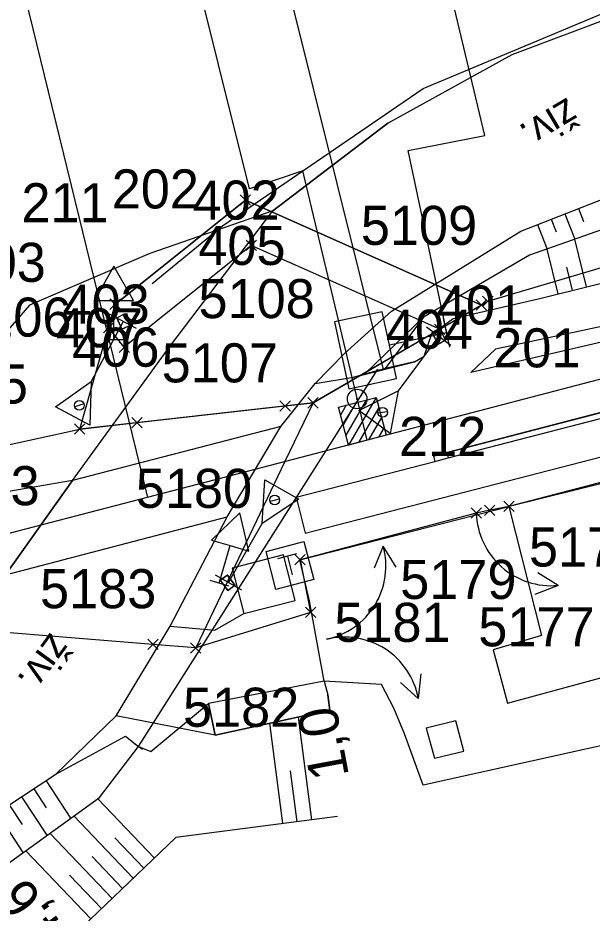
# Model space of a CAD drawing. Extents: x -806456 to -805395, y -1150847 to -1150506.
# Drawn here: x -806176.16 to -806146.78, y -1150729.15 to -1150683.33 of the extents above; entities that cross this region are included whole.
import ezdxf

# ---------------------------------------------------------------- set-up
doc = ezdxf.new("R2010")
doc.units = 0
for name, color, linetype in [('0381KM032-037P - Vrstva 1', 7, 'Continuous'), ('0381KM032-037P - Vrstva 12', 7, 'Continuous'), ('0381KM032-037P - Vrstva 14', 7, 'Continuous'), ('0381KM032-037P - Vrstva 16', 7, 'Continuous'), ('0381KM032-037P - Vrstva 17', 7, 'Continuous'), ('0381KM032-037P - Vrstva 19', 7, 'Continuous'), ('0381KM032-037P - Vrstva 23', 7, 'Continuous'), ('0381KM032-037P - Vrstva 27', 7, 'Continuous'), ('0381KM032-037P - Vrstva 3', 7, 'Continuous'), ('0381KM032-037P - Vrstva 33', 7, 'Continuous'), ('0381KM032-037P - Vrstva 4', 7, 'Continuous'), ('0381KM032-037P - Vrstva 48', 7, 'Continuous'), ('0381KM032-037P - Vrstva 49', 7, 'Continuous'), ('0381KM032-037P - Vrstva 51', 7, 'Continuous'), ('0381KM032-037P - Vrstva 55', 7, 'Continuous'), ('0381KM032-037P - Vrstva 7', 7, 'Continuous'), ('DZ - DZ_krizek', 7, 'Continuous'), ('DZ - DZ_ostat', 7, 'Continuous'), ('DZ - DZ_číslo', 7, 'Continuous'), ('szdc - hran DP', 7, 'Continuous'), ('szdc - szdc_cislo', 7, 'Continuous'), ('szdc - szdc_krizek', 7, 'Continuous'), ('VB - VB', 7, 'Continuous'), ('VB - VB_cislo', 7, 'Continuous'), ('VB - VB_krizek', 7, 'Continuous')]:
    doc.layers.add(name, color=color, linetype=linetype)

msp = doc.modelspace()

# ---------------------------------------------------------------- linework, layer by layer
at = {"layer": '0381KM032-037P - Vrstva 1'}
msp.add_lwpolyline([(-805989.76, -1150661.17), (-806027.03, -1150670.9), (-806064.32, -1150680.56), (-806101.67, -1150690.24), (-806138.44, -1150699.75), (-806158.28, -1150704.94), (-806163.64, -1150706.34), (-806175.38, -1150709.4), (-806186.46, -1150712.29), (-806205.201, -1150717.188), (-806213.26, -1150719.29)], dxfattribs=at)
at = {"layer": '0381KM032-037P - Vrstva 12'}
for p, q in [((-806171.097, -1150698.685), (-806170.698, -1150698.477)), ((-806170.424, -1150699.073), (-806170.42, -1150699.072)), ((-806154.576, -1150699.231), (-806154.576, -1150699.231)), ((-806154.655, -1150700.027), (-806154.654, -1150700.027)), ((-806165.431, -1150711.842), (-806165.798, -1150712.11)), ((-806165.431, -1150711.842), (-806165.452, -1150711.852)), ((-806165.431, -1150711.842), (-806165.054, -1150712.367)), ((-806165.411, -1150712.643), (-806165.409, -1150712.642))]:
    msp.add_line(p, q, dxfattribs=at)
for points in [[(-806171.096, -1150698.684), (-806170.697, -1150698.478), (-806170.42, -1150699.072), (-806170.837, -1150699.265), (-806171.096, -1150698.684), (-806171.097, -1150698.685), (-806170.836, -1150699.265), (-806170.837, -1150699.265)], [(-806170.836, -1150699.265), (-806170.424, -1150699.073), (-806170.698, -1150698.477), (-806170.697, -1150698.478)], [(-806154.955, -1150699.45), (-806154.576, -1150699.231), (-806154.27, -1150699.815), (-806154.654, -1150700.027), (-806154.955, -1150699.45), (-806154.958, -1150699.45), (-806154.655, -1150700.027), (-806154.267, -1150699.814), (-806154.27, -1150699.815)], [(-806154.267, -1150699.814), (-806154.576, -1150699.231), (-806154.958, -1150699.45)], [(-806165.796, -1150712.109), (-806165.452, -1150711.852), (-806165.062, -1150712.372), (-806165.411, -1150712.643), (-806165.796, -1150712.109), (-806165.798, -1150712.11), (-806165.409, -1150712.642), (-806165.054, -1150712.367), (-806165.062, -1150712.372)]]:
    msp.add_lwpolyline(points, dxfattribs=at)
at = {"layer": '0381KM032-037P - Vrstva 14'}
for p, q in [((-806161.449, -1150709.693), (-806093.878, -1150692.3)), ((-806154.198, -1150705.574), (-806154.133, -1150705.838)), ((-806161.922, -1150707.857), (-806154.816, -1150706.033)), ((-806161.922, -1150707.857), (-806161.449, -1150709.693))]:
    msp.add_line(p, q, dxfattribs=at)
for points in [[(-806154.886, -1150705.756), (-806154.199, -1150705.575), (-806132.573, -1150699.952), (-806108.128, -1150693.694), (-806094.432, -1150690.13), (-806092.838, -1150689.765), (-806094.431, -1150690.13), (-806108.117, -1150693.693), (-806132.574, -1150699.948), (-806154.198, -1150705.574), (-806154.884, -1150705.755)], [(-806154.816, -1150706.033), (-806154.133, -1150705.838), (-806132.472, -1150700.244), (-806108.057, -1150693.975), (-806094.307, -1150690.424), (-806092.667, -1150690.003)], [(-806154.816, -1150706.033), (-806154.137, -1150705.844), (-806132.472, -1150700.244)], [(-806154.886, -1150705.756), (-806154.884, -1150705.755), (-806154.816, -1150706.033)]]:
    msp.add_lwpolyline(points, dxfattribs=at)
at = {"layer": '0381KM032-037P - Vrstva 16'}
for p, q in [((-806160.478, -1150717.283), (-806166.409, -1150718.419)), ((-806160.198, -1150718.758), (-806160.293, -1150717.983)), ((-806166.409, -1150718.419), (-806166.069, -1150720.047)), ((-806166.069, -1150720.047), (-806160.198, -1150718.758))]:
    msp.add_line(p, q, dxfattribs=at)
msp.add_lwpolyline([(-806166.069, -1150720.047), (-806171.128, -1150719.056), (-806168.37, -1150714.464), (-806166.085, -1150714.657), (-806164.602, -1150713.817)], dxfattribs=at)
msp.add_lwpolyline([(-806153.75, -1150719.31), (-806155.265, -1150719.685), (-806154.836, -1150721.222), (-806153.334, -1150720.858)], close=True, dxfattribs=at)
at = {"layer": '0381KM032-037P - Vrstva 17'}
for q in [(-806149.551, -1150711.723), (-806149.698, -1150712.832)]:
    msp.add_line((-806148.519, -1150712.375), q, dxfattribs=at)
for points in [[(-806169.284, -1150696.914), (-806165.684, -1150693.969), (-806155.413, -1150686.939), (-806141.029, -1150680.901), (-806121.846, -1150675.136), (-806106.33, -1150670.053), (-806095.392, -1150665.453)], [(-806160.478, -1150717.283), (-806161.235, -1150713.172), (-806161.722, -1150711.057), (-806151.035, -1150708.341)], [(-806156.804, -1150711.439), (-806157.463, -1150710.359), (-806157.921, -1150711.49)], [(-806155.547, -1150716.896), (-806155.668, -1150718.155), (-806156.574, -1150717.337)]]:
    msp.add_lwpolyline(points, dxfattribs=at)
for centre, start, end in [((-806148.868, -1150708.556), 181.714, 275.2338), ((-806161.159, -1150711.38), 281.9322, 15.4521), ((-806159.438, -1150718.852), 10.4818, 104.0016)]:
    msp.add_arc(centre, 3.834, start, end, dxfattribs=at)
at = {"layer": '0381KM032-037P - Vrstva 19'}
for p, q in [((-806157.446, -1150701.329), (-806169.593, -1150652.631)), ((-806169.987, -1150720.615), (-806157.733, -1150701.3)), ((-806158.404, -1150701.543), (-806157.373, -1150701.28)), ((-806158.4, -1150701.548), (-806158.404, -1150701.543)), ((-806157.368, -1150701.279), (-806157.373, -1150701.28)), ((-806170.188, -1150720.467), (-806169.786, -1150720.763))]:
    msp.add_line(p, q, dxfattribs=at)
for points in [[(-806158.982, -1150701.712), (-806155.863, -1150700.934), (-806157.368, -1150701.279)], [(-806158.982, -1150701.712), (-806158.4, -1150701.548)]]:
    msp.add_lwpolyline(points, dxfattribs=at)
at = {"layer": '0381KM032-037P - Vrstva 23'}
for points in [[(-806142.07, -1150715.951), (-806143.104, -1150712.223), (-806134.891, -1150710.09), (-806136.286, -1150704.548), (-806144.528, -1150706.669), (-806144.577, -1150706.639), (-806151.035, -1150708.341), (-806149.366, -1150714.939), (-806151.841, -1150715.669), (-806151.103, -1150718.404)], [(-806162.56, -1150710.816), (-806165.198, -1150711.492), (-806164.602, -1150713.817), (-806161.964, -1150713.141)]]:
    msp.add_lwpolyline(points, close=True, dxfattribs=at)
at = {"layer": '0381KM032-037P - Vrstva 27'}
msp.add_line((-806158.849, -1150702.829), (-806158.749, -1150702.829), dxfattribs=at)
msp.add_circle((-806158.799, -1150702.829), 0.5, dxfattribs=at)
at = {"layer": '0381KM032-037P - Vrstva 3'}
for p, q in [((-806158.331, -1150702.886), (-806159.381, -1150704.68)), ((-806157.818, -1150702.752), (-806159.248, -1150705.193)), ((-806159.357, -1150703.154), (-806159.65, -1150703.653)), ((-806158.844, -1150703.02), (-806159.516, -1150704.166)), ((-806157.684, -1150703.265), (-806158.735, -1150705.059)), ((-806157.55, -1150703.779), (-806158.221, -1150704.925)), ((-806157.416, -1150704.292), (-806157.708, -1150704.791))]:
    msp.add_line(p, q, dxfattribs=at)
msp.add_lwpolyline([(-806158.28, -1150704.94), (-806161.571, -1150691.159), (-806164.309, -1150692.072), (-806173.835, -1150653.806)], dxfattribs=at)
msp.add_lwpolyline([(-806157.312, -1150704.687), (-806159.248, -1150705.193), (-806159.753, -1150703.258), (-806157.818, -1150702.752)], close=True, dxfattribs=at)
at = {"layer": '0381KM032-037P - Vrstva 33'}
for p, q in [((-806162.85, -1150710.997), (-806161.882, -1150710.745)), ((-806162.366, -1150710.871), (-806162.114, -1150711.839))]:
    msp.add_line(p, q, dxfattribs=at)
msp.add_lwpolyline([(-806163.46, -1150710.64), (-806161.525, -1150710.135), (-806161.02, -1150712.07), (-806162.955, -1150712.575), (-806163.46, -1150710.64)], dxfattribs=at)
at = {"layer": '0381KM032-037P - Vrstva 4'}
for p, q in [((-806169.501, -1150707.868), (-806182.162, -1150656.159)), ((-806170.089, -1150699.232), (-806171.461, -1150698.498)), ((-806154, -1150700.092), (-806155.244, -1150699.156)), ((-806172.782, -1150703.087), (-806173.251, -1150703.226)), ((-806157.253, -1150703.488), (-806157.738, -1150703.554)), ((-806163.25, -1150708.061), (-806162.777, -1150707.935)), ((-806166.06, -1150711.832), (-806164.71, -1150712.606))]:
    msp.add_line(p, q, dxfattribs=at)
for points in [[(-806107.829, -1150689.094), (-806118.691, -1150691.974), (-806137.278, -1150697.201), (-806151.726, -1150700.277), (-806152.972, -1150701.484)], [(-806107.781, -1150690.049), (-806118.339, -1150693.119), (-806137.186, -1150697.806), (-806152.972, -1150701.484)], [(-806170.775, -1150698.865), (-806172.404, -1150701.937), (-806172.472, -1150704.171), (-806174.24, -1150703.24), (-806172.404, -1150701.937)], [(-806154.622, -1150699.624), (-806156.703, -1150702.409), (-806157.114, -1150704.607), (-806158.718, -1150703.416), (-806156.703, -1150702.409)], [(-806173.358, -1150707), (-806179.992, -1150708.144), (-806186.437, -1150710.716), (-806215.256, -1150718.168), (-806230.349, -1150722.089), (-806238.693, -1150724.411)], [(-806165.385, -1150712.219), (-806163.663, -1150709.198), (-806163.526, -1150706.967), (-806161.788, -1150707.952), (-806163.663, -1150709.198)]]:
    msp.add_lwpolyline(points, dxfattribs=at)
msp.add_lwpolyline([(-806165.452, -1150708.868), (-806162.708, -1150704.236), (-806173.358, -1150707), (-806176.794, -1150711.837)], close=True, dxfattribs=at)
for centre in [(-806173.016, -1150703.155), (-806157.495, -1150703.519), (-806163.014, -1150707.999)]:
    msp.add_circle(centre, 0.248, dxfattribs=at)
at = {"layer": '0381KM032-037P - Vrstva 48'}
for p, q in [((-806147.468, -1150693.088), (-806147.21, -1150693.749)), ((-806148.865, -1150693.634), (-806148.616, -1150694.271)), ((-806148.167, -1150693.361), (-806147.66, -1150694.659)), ((-806149.564, -1150693.907), (-806149.076, -1150695.157)), ((-806147.054, -1150697.098), (-806147.659, -1150694.659)), ((-806148.51, -1150697.459), (-806149.081, -1150695.159)), ((-806147.782, -1150697.279), (-806148.076, -1150696.094)), ((-806162.608, -1150724.567), (-806163.272, -1150719.433)), ((-806161.12, -1150724.375), (-806161.801, -1150719.11)), ((-806161.864, -1150724.471), (-806162.2, -1150721.871)), ((-806174.716, -1150722.377), (-806173.459, -1150724.29)), ((-806175.343, -1150722.788), (-806174.706, -1150723.758)), ((-806175.97, -1150723.2), (-806174.679, -1150725.165)), ((-806169.169, -1150726.326), (-806172.068, -1150723.292)), ((-806176.597, -1150723.612), (-806175.943, -1150724.607)), ((-806177.223, -1150724.024), (-806175.899, -1150726.04)), ((-806170.253, -1150727.362), (-806173.299, -1150724.175)), ((-806171.338, -1150728.398), (-806174.53, -1150725.058)), ((-806169.711, -1150726.844), (-806171.197, -1150725.288)), ((-806172.423, -1150729.435), (-806175.761, -1150725.941)), ((-806170.796, -1150727.88), (-806172.355, -1150726.248)), ((-806171.88, -1150728.916), (-806173.513, -1150727.208))]:
    msp.add_line(p, q, dxfattribs=at)
at = {"layer": '0381KM032-037P - Vrstva 49'}
for q in [(-806158.4, -1150701.548), (-806157.368, -1150701.279)]:
    msp.add_line((-806155.41, -1150698.652), q, dxfattribs=at)
for points in [[(-806106.833, -1150681.791), (-806120.865, -1150686.009), (-806130.84, -1150689.204), (-806140.721, -1150692.217), (-806149.976, -1150695.474), (-806155.41, -1150698.652)], [(-806160.94, -1150702.044), (-806159.44, -1150700.497), (-806157.039, -1150698.345), (-806150.424, -1150694.243), (-806141.479, -1150690.749), (-806131.125, -1150687.358), (-806121.483, -1150684.155)], [(-806155.863, -1150700.934), (-806155.366, -1150700.637), (-806154.958, -1150699.45), (-806154.576, -1150699.231), (-806153.885, -1150698.711), (-806149.376, -1150697.674), (-806139.489, -1150695.222), (-806130.934, -1150692.921), (-806118.589, -1150689.919), (-806108.264, -1150688.165)], [(-806157.224, -1150688.717), (-806163.106, -1150693.208), (-806169.402, -1150695.384), (-806175.562, -1150698.028), (-806181.812, -1150705.214), (-806196.093, -1150709.847), (-806203.772, -1150712.233), (-806204.393, -1150713.538)], [(-806086.941, -1150691.888), (-806103.092, -1150696.78), (-806110.097, -1150699.269), (-806113.941, -1150700.3), (-806116.978, -1150701.29), (-806117.569, -1150702.15), (-806117.466, -1150702.7), (-806118.52, -1150712.146), (-806144.328, -1150720.147), (-806155.423, -1150722.604), (-806156.372, -1150719.964), (-806156.921, -1150718.664), (-806157.558, -1150717.448), (-806160.478, -1150717.283), (-806160.293, -1150717.983), (-806160.198, -1150718.758), (-806166.069, -1150720.047), (-806166.409, -1150718.419)], [(-806160.94, -1150702.044), (-806158.982, -1150701.712)], [(-806169.987, -1150720.615), (-806169.362, -1150720.879), (-806166.409, -1150718.419)], [(-806174.208, -1150722.043), (-806170.645, -1150720.091), (-806169.987, -1150720.615)], [(-806193.249, -1150733.077), (-806185.745, -1150730.772), (-806177.154, -1150726.94), (-806171.988, -1150723.234), (-806169.987, -1150720.615)], [(-806194.182, -1150731.583), (-806186.226, -1150728.982), (-806178.594, -1150724.924), (-806174.208, -1150722.043)], [(-806159.8, -1150724.204), (-806168.067, -1150725.273), (-806174.063, -1150731.002)]]:
    msp.add_lwpolyline(points, dxfattribs=at)
at = {"layer": '0381KM032-037P - Vrstva 51'}
for p, q in [((-806171.742, -1150699.79), (-806170.742, -1150699.79)), ((-806166.34, -1150712.113), (-806165.38, -1150712.395))]:
    msp.add_line(p, q, dxfattribs=at)
for points in [[(-806195.218, -1150723.443), (-806183.651, -1150718.077), (-806179.484, -1150714.678), (-806176.794, -1150711.837), (-806173.358, -1150707), (-806168.375, -1150700.145), (-806163.106, -1150693.208), (-806157.224, -1150688.717), (-806150.874, -1150685.207), (-806140.159, -1150681.153)], [(-806194.182, -1150731.583), (-806186.226, -1150728.982), (-806178.594, -1150724.924), (-806174.208, -1150722.043), (-806171.128, -1150719.056), (-806168.37, -1150714.464), (-806165.452, -1150708.868), (-806162.708, -1150704.236), (-806160.94, -1150702.044), (-806159.44, -1150700.497), (-806157.039, -1150698.345), (-806150.424, -1150694.243), (-806141.479, -1150690.749), (-806131.125, -1150687.358), (-806121.483, -1150684.155)], [(-806171.242, -1150699.79), (-806171.242, -1150697.79), (-806170.242, -1150697.79), (-806171.242, -1150696.04), (-806172.242, -1150697.79), (-806171.242, -1150697.79)], [(-806165.86, -1150712.254), (-806165.296, -1150710.335), (-806164.337, -1150710.617), (-806164.803, -1150708.656), (-806166.256, -1150710.053), (-806165.296, -1150710.335)]]:
    msp.add_lwpolyline(points, dxfattribs=at)
at = {"layer": '0381KM032-037P - Vrstva 55'}
msp.add_lwpolyline([(-806161.05, -1150703.03), (-806162.49, -1150706.04), (-806167.06, -1150715.57)], dxfattribs=at)
at = {"layer": '0381KM032-037P - Vrstva 7'}
msp.add_line((-806154.057, -1150700.177), (-806154.373, -1150698.711), dxfattribs=at)
for points in [[(-806154.215, -1150699.444), (-806156.181, -1150690.115), (-806152.272, -1150689.343), (-806161.508, -1150650.617)], [(-806154.215, -1150699.444), (-806157.148, -1150700.076), (-806157.516, -1150698.365), (-806159.96, -1150698.892), (-806159.223, -1150702.313), (-806156.779, -1150701.787), (-806157.148, -1150700.076)]]:
    msp.add_lwpolyline(points, dxfattribs=at)
at = {"layer": 'DZ - DZ_krizek'}
for p, q in [((-806164.249, -1150692.916), (-806164.78, -1150692.386)), ((-806164.78, -1150692.916), (-806164.249, -1150692.386)), ((-806170.919, -1150698.26), (-806171.45, -1150697.73)), ((-806171.45, -1150698.26), (-806170.919, -1150697.73)), ((-806170.898, -1150698.243), (-806171.429, -1150697.713)), ((-806171.429, -1150698.243), (-806170.898, -1150697.713)), ((-806152.178, -1150698.289), (-806152.709, -1150697.759)), ((-806152.709, -1150698.289), (-806152.178, -1150697.759)), ((-806160.785, -1150703.295), (-806161.316, -1150702.765)), ((-806161.316, -1150703.295), (-806160.785, -1150702.765)), ((-806172.725, -1150704.635), (-806173.256, -1150704.105)), ((-806173.256, -1150704.635), (-806172.725, -1150704.105))]:
    msp.add_line(p, q, dxfattribs=at)
at = {"layer": 'DZ - DZ_ostat'}
for points in [[(-806171.163, -1150697.978), (-806164.514, -1150692.651), (-806152.443, -1150698.024), (-806161.05, -1150703.03), (-806172.99, -1150704.37), (-806171.184, -1150697.995)], [(-806152.443, -1150698.024), (-806164.514, -1150692.651), (-806171.184, -1150697.995)]]:
    msp.add_lwpolyline(points, dxfattribs=at)
at = {"layer": 'szdc - hran DP'}
for p, q in [((-806152.11, -1150697.83), (-806107.35, -1150684.54)), ((-806161.05, -1150703.03), (-806152.11, -1150697.83)), ((-806170.06, -1150704.04), (-806162.48, -1150703.19)), ((-806162.48, -1150703.19), (-806161.05, -1150703.03)), ((-806172.99, -1150704.37), (-806170.06, -1150704.04)), ((-806238.93, -1150718.822), (-806172.99, -1150704.37)), ((-806136.51, -1150704.75), (-806151.02, -1150708.33)), ((-806151.02, -1150708.33), (-806152.01, -1150708.53)), ((-806152.7, -1150708.67), (-806161.72, -1150711.06)), ((-806152.01, -1150708.53), (-806152.7, -1150708.67)), ((-806161.72, -1150711.06), (-806161.18, -1150713.76)), ((-806161.18, -1150713.76), (-806167.06, -1150715.57)), ((-806169.25, -1150715.39), (-806177.96, -1150714.69)), ((-806167.06, -1150715.57), (-806169.25, -1150715.39))]:
    msp.add_line(p, q, dxfattribs=at)
at = {"layer": 'szdc - szdc_krizek'}
for p, q in [((-806151.845, -1150698.095), (-806152.376, -1150697.565)), ((-806152.376, -1150698.095), (-806151.845, -1150697.565)), ((-806162.215, -1150703.455), (-806162.746, -1150702.925)), ((-806162.746, -1150703.455), (-806162.215, -1150702.925)), ((-806160.785, -1150703.295), (-806161.316, -1150702.765)), ((-806161.316, -1150703.295), (-806160.785, -1150702.765)), ((-806169.795, -1150704.305), (-806170.326, -1150703.775)), ((-806170.326, -1150704.305), (-806169.795, -1150703.775)), ((-806172.725, -1150704.635), (-806173.256, -1150704.105)), ((-806173.256, -1150704.635), (-806172.725, -1150704.105)), ((-806152.435, -1150708.935), (-806152.966, -1150708.405)), ((-806152.966, -1150708.935), (-806152.435, -1150708.405)), ((-806151.745, -1150708.795), (-806152.276, -1150708.265)), ((-806152.276, -1150708.795), (-806151.745, -1150708.265)), ((-806150.755, -1150708.595), (-806151.286, -1150708.065)), ((-806151.286, -1150708.595), (-806150.755, -1150708.065)), ((-806161.455, -1150711.325), (-806161.986, -1150710.795)), ((-806161.986, -1150711.325), (-806161.455, -1150710.795)), ((-806160.915, -1150714.025), (-806161.446, -1150713.495)), ((-806161.446, -1150714.025), (-806160.915, -1150713.495)), ((-806168.985, -1150715.655), (-806169.516, -1150715.125)), ((-806169.516, -1150715.655), (-806168.985, -1150715.125)), ((-806166.795, -1150715.835), (-806167.326, -1150715.305)), ((-806167.326, -1150715.835), (-806166.795, -1150715.305))]:
    msp.add_line(p, q, dxfattribs=at)
at = {"layer": 'VB - VB'}
for points in [[(-806152.443, -1150698.024), (-806164.514, -1150692.651), (-806171.163, -1150697.978)], [(-806152.443, -1150698.024), (-806154.575, -1150699.264), (-806164.215, -1150694.974), (-806170.714, -1150700.181), (-806171.509, -1150699.188), (-806171.163, -1150697.978)]]:
    msp.add_lwpolyline(points, dxfattribs=at)
at = {"layer": 'VB - VB_krizek'}
for p, q in [((-806164.249, -1150692.916), (-806164.78, -1150692.386)), ((-806164.78, -1150692.916), (-806164.249, -1150692.386)), ((-806163.95, -1150695.239), (-806164.481, -1150694.709)), ((-806164.481, -1150695.239), (-806163.95, -1150694.709)), ((-806170.898, -1150698.243), (-806171.429, -1150697.713)), ((-806171.429, -1150698.243), (-806170.898, -1150697.713)), ((-806152.178, -1150698.289), (-806152.709, -1150697.759)), ((-806152.709, -1150698.289), (-806152.178, -1150697.759)), ((-806171.244, -1150699.453), (-806171.775, -1150698.923)), ((-806171.775, -1150699.453), (-806171.244, -1150698.923)), ((-806154.31, -1150699.529), (-806154.841, -1150698.999)), ((-806154.841, -1150699.529), (-806154.31, -1150698.999)), ((-806170.449, -1150700.446), (-806170.98, -1150699.916)), ((-806170.98, -1150700.446), (-806170.449, -1150699.916))]:
    msp.add_line(p, q, dxfattribs=at)

# ---------------------------------------------------------------- texts
at = {"layer": '0381KM032-037P - Vrstva 23'}
msp.add_text('zast. Vimperk', height=8, rotation=195, dxfattribs=at).set_placement((-806086.067, -1150728.443))
at = {"layer": '0381KM032-037P - Vrstva 48'}
for s, rotation, p in [('1,0', 100.6308, (-806159.21, -1150722.113)), ('4,6', 126.74, (-806173.521, -1150730.195))]:
    msp.add_text(s, height=2, rotation=rotation, dxfattribs=at).set_placement(p)
at = {"layer": '0381KM032-037P - Vrstva 51'}
for rotation, p in [(210.724, (-806148.035, -1150687.371)), (233.986, (-806174.484, -1150714.734))]:
    msp.add_text('živ.', height=1.5, rotation=rotation, dxfattribs=at).set_placement(p)
at = {"layer": 'DZ - DZ_číslo'}
for s, p in [('202', (-806171.355, -1150693.082)), ('211', (-806175.976, -1150693.789)), ('203', (-806179.191, -1150696.837)), ('201', (-806151.835, -1150701.215)), ('212', (-806156.654, -1150705.745)), ('213', (-806179.506, -1150708.269))]:
    msp.add_text(s, height=2, dxfattribs=at).set_placement(p)
at = {"layer": 'szdc - szdc_cislo'}
for s, p in [('5109', (-806158.607, -1150694.946)), ('5108', (-806166.916, -1150698.696)), ('5106', (-806179.362, -1150699.642)), ('5107', (-806168.801, -1150701.983)), ('5105', (-806181.593, -1150703.065)), ('5180', (-806170.124, -1150708.406)), ('5178', (-806150.005, -1150711.41)), ('5179', (-806156.595, -1150713.068)), ('5183', (-806175.024, -1150713.542)), ('5181', (-806159.966, -1150715.263)), ('5177', (-806152.598, -1150715.492)), ('5182', (-806167.709, -1150719.609))]:
    msp.add_text(s, height=2, dxfattribs=at).set_placement(p)
at = {"layer": 'VB - VB_cislo'}
for s, p in [('402', (-806167.222, -1150693.651)), ('405', (-806166.923, -1150695.974)), ('403', (-806173.871, -1150698.978)), ('401', (-806154.718, -1150699.024)), ('407', (-806174.225, -1150700.188)), ('404', (-806157.331, -1150700.264)), ('406', (-806173.375, -1150701.181))]:
    msp.add_text(s, height=2, dxfattribs=at).set_placement(p)

doc.saveas('drawing.dxf')
